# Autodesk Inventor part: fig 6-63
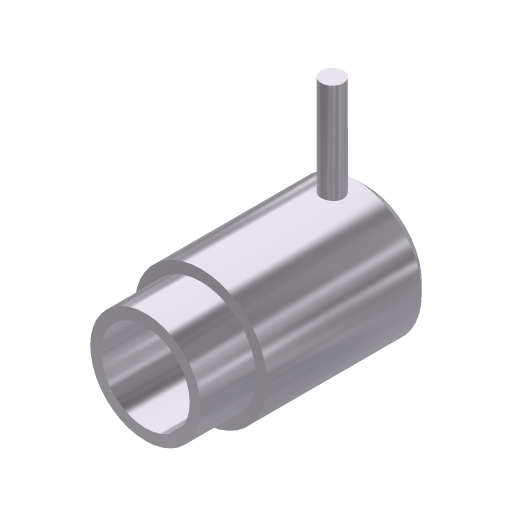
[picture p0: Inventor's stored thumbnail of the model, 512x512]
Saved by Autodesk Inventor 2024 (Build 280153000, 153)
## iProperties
Shininess: 77.0
Angle Display Precision: 2
Document Length Units: 11269
Document Angle Units: 11279
Document Time Units: 11290
Document Mass Units: 11283
Document Length Units Precision: 3
Document Angle Units Precision: 2
Compacted: True
Created: 2001-12
Part Number: fig 6-63
Document SubType Name: Modeling
Designer: Renu Muthoo
Density: 1 g/cm^3
Material: Generic
Appearance: Metal-AL-6061 (Polished)
Density: 0.0
Volumn: 0.0
Area: 0.0
PropertySet Name: Model Information
Control State: 0
Master: False
Checked Out: False
Author: Renu Muthoo
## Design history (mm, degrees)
sketch "Sketch2"
  geometry: L1 (-9.573, -4.327)-(-9.573, -5.327); L2 (-9.573, -5.327)-(-4.573, -5.327); L3 (-4.573, -5.327)-(-4.573, -6.327); L4 (-4.573, -6.327)-(9.427, -6.327); L5 (9.427, -6.327)-(10.427, -5.327); L6 (10.427, -5.327)-(10.427, -4.327); L7 (10.427, -4.327)-(-9.573, -4.327); L8 (-13.687, -0.327)-(14, -0.327)
  constraints: 16 end point, 5 parallel, 1 perpendicular, 1 vertical
  dimensions: "d9" = 20 distance of L6.end L1.start; "d10" = 5 distance of L1.end L2.end; "d11" = 12 diameter of L4 L8; "d12" = 10 diameter of L2 L8; "d13" = 8 diameter of L7 L8; "d14" = 45 deg angle of L5 L4; "d15" = 1 horizontal distance of L5.end L4.end
revolve "Revolution2" sketch "Sketch2" stored, may be unused: angle "d16" = 90 deg
workplane "Work Plane1"
workplane "Work Plane2"
sketch "Sketch3"
  geometry: L1 (-4, 8)-(4, 8) reference; C1 r 1 at (-0.098, 5)
  constraints: 1 centre point
  dimensions: "d18" = 3 distance from line of L1 C1.centre; "d19" = 2 diameter of C1
extrude "Extrusion1" join sketch "Sketch3" distance "d20" = 10; taper "d21" = 0 deg
body "Solid1"
other parameters: "d17" = -1
